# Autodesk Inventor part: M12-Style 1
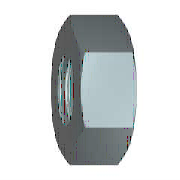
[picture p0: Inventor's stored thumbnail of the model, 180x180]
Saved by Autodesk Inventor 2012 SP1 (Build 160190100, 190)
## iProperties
Created: 2006-02
Material: Steel, Mild
Description: Hex Nut
Document SubType Name: Modeling
Standard: ANSI B 18.2.4.1 M
Designer: Administrator
Standards Organization: ANSI
Language: en-US
Categories: <MemberInstance><Categories><Category DisplayName="Fasteners" InternalName="e4da775c-781d-43d5-af7c-5136215cf5a6" Mnemonic="FSTN"><Category DisplayName="Nuts" I
Density: 1 g/cm^3
Author: Administrator
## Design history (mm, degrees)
workaxis "Work Axis1"
workplane "Work Plane1"
sketch "Sketch1"
  geometry: L1 (-10.392, 0)-(-5.196, 9); L2 (-5.196, 9)-(5.196, 9); L3 (5.196, 9)-(10.392, 0); L4 (10.392, 0)-(5.196, -9); L5 (5.196, -9)-(-5.196, -9); L6 (-5.196, -9)-(-10.392, 0); 2 further points
  constraints: 12 end point, 1 coincident, 1 horizontal, 11 other
  dimensions: "d0" = 20.78461 distance of L3.end L1.start (= 1.1547 x SW)
extrude "Body" new body sketch "Sketch1" distance "d1" = 10.8 (= KOH); taper "d2" = 0 deg
revolve "Chamfer1" stored, may be unused: angle "d7" = 90 deg
sketch "Sketch3"
  geometry: A1 r 9 centre (0, 0) between (-4.5, -7.794) and (4.5, -7.794) reference; 1 further point
  constraints: 1 coincident
hole "Thread" sketch "Sketch3" diameter "d25" = 10.106; stored, may be unused: countersink angle "d29" = 82 deg, drill point angle "d31" = 118 deg; dims "d26" = 6, "d27" = 4, "d28" = 2, "d30" = 8
body "Solid1"
chamfer "Chamfer2" distance "d8" = 0.94722 (= -0.5 x GD1 + 0.5 x NND); stored, may be unused: angle "d9" = 30 deg, second distance "d40" = 0.94722 (= -0.5 x GD1 + 0.5 x NND)
chamfer "Chamfer3" distance "d10" = 0.94722 (= -0.5 x GD1 + 0.5 x NND); stored, may be unused: angle "d11" = 30 deg, second distance "d41" = 0.94722 (= -0.5 x GD1 + 0.5 x NND)
sketch "Sketch2"
  geometry: L1 (0, 5.196)-(0, 10.392) reference; L2 (0, 10.392)-(10.8, 10.392) reference; L3 (10.8, 5.196)-(10.8, 10.392) reference; L4 (-2.16, 0)-(12.96, 0) reference; L5 (0.649, 10.392)-(0, 9); L6 (10.151, 10.392)-(10.8, 9)
  constraints: 4 end point, 4 point on line
  dimensions: "d3" = 25 deg angle of L1 L5 (= ANG1); "d4" = 25 deg angle of L3 L6 (= ANG2); "d5" = 18 diameter of L5.end L4 (= SW0); "d6" = 18 diameter of L6.end L4 (= SW01)
other parameters: "ANG1" = 25 deg [user parameter; used in 1 equation term], "ANG2" = 25 deg [user parameter; used in 1 equation term], "NND" = 12 [user parameter; used in 4 equation terms], "KOH" = 10.8 [user parameter; used in 1 equation term], "SW" = 18 [user parameter; used in 4 equation terms], "SW0" = 18 (= SW) [user parameter; used in 1 equation term], "SW01" = 18 (= SW) [user parameter; used in 1 equation term], "GD1" = 10.10557 (computed from THREADDIA, PTC, TOA) [user parameter; used in 4 equation terms], "d13" = 0, "d14" = 0, "d39" = 0, "d42" = 0, "GUL" = 0.94722 (= 0.541266 x PTC) [user parameter], "TPU" = 5.71429 (computed from PTC) [user parameter], "THREADDIA" = 12 [user parameter; used in 1 equation term], "TOA" = 30 deg [user parameter; used in 1 equation term], "PTC" = 1.75 [user parameter; used in 4 equation terms], "E0" = 20.79 (= 1.155 x SW) [user parameter], "GAL" = 0.94722 (= 0.541266 x PTC) [user parameter]
